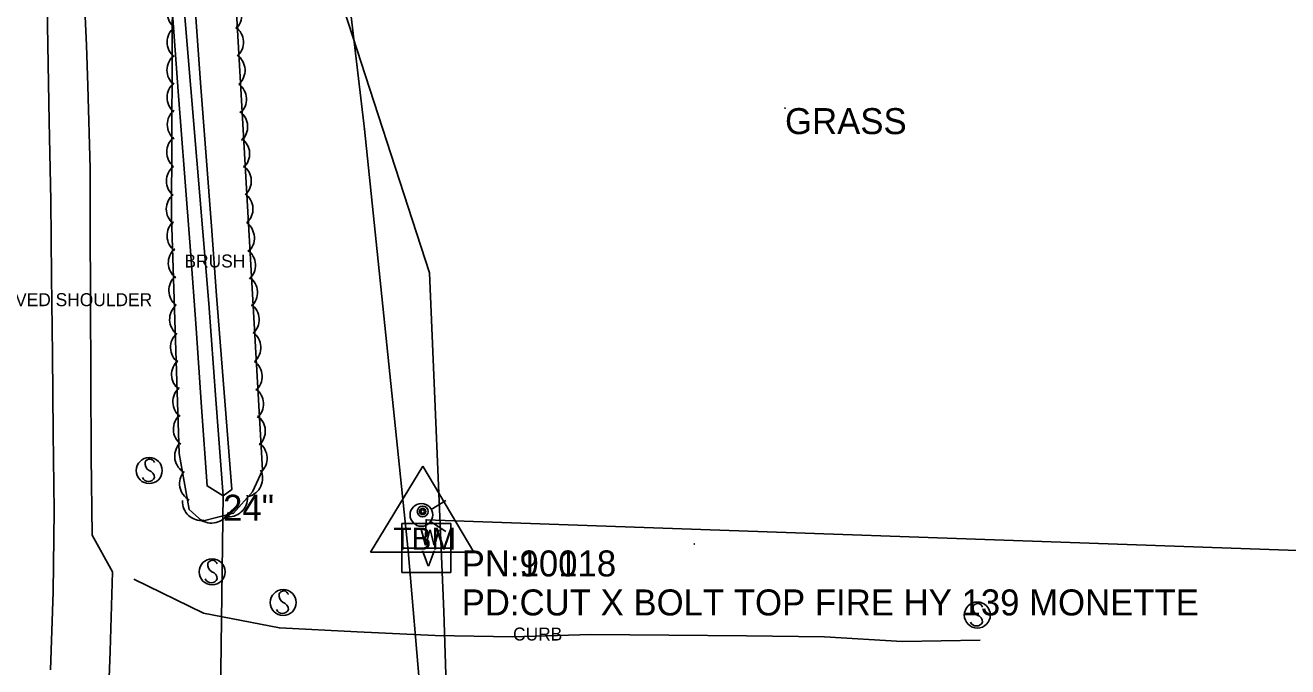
# Model space of a CAD drawing. Extents: x 1802180 to 1804859, y 572524 to 575172.
# Drawn here: x 1803540.3 to 1803783.3, y 574122.9 to 574246.4 of the extents above; entities that cross this region are included whole.
import ezdxf

# ---------------------------------------------------------------- set-up
doc = ezdxf.new("R2010")
doc.units = 0
for name, color, linetype in [('EX_EDGE_PAVEMENT', 7, 'Continuous'), ('EX_SHOULDER', 7, 'Continuous'), ('S_CURB_ANNOT', 7, 'Continuous'), ('S_DITCHLINE', 7, 'Continuous'), ('S_DRG_PT_SYM', 7, 'Continuous'), ('S_EDGE_PAVEMENT', 7, 'Continuous'), ('S_GAS_UTILITIES', 7, 'Continuous'), ('S_MSC_PT_SYM', 7, 'Continuous'), ('S_PRIMARY_CTL', 7, 'Continuous'), ('S_PRIMARY_CTL_ANNOT', 7, 'Continuous'), ('S_SHOULDER_ANNOT', 7, 'Continuous'), ('S_SIDE_DRAIN', 7, 'Continuous'), ('S_SIDE_DRAIN_ANNOT', 7, 'Continuous'), ('S_SIGN', 7, 'Continuous'), ('S_SURVEY_TEXT_ANNOT', 7, 'Continuous'), ('S_TREE', 7, 'Continuous'), ('S_TREE_ANNOT', 7, 'Continuous'), ('S_UTL_PT_SYM', 7, 'Continuous'), ('S_WATER_UTILITIES', 7, 'Continuous')]:
    doc.layers.add(name, color=color, linetype=linetype)

msp = doc.modelspace()

# ---------------------------------------------------------------- linework, layer by layer
at = {"layer": 'EX_EDGE_PAVEMENT'}
msp.add_lwpolyline([(1803545.13, 574122.38), (1803545.67, 574137.37), (1803545.82, 574152.93), (1803545.67, 574167.93), (1803545.52, 574183), (1803545.32, 574198), (1803545.22, 574212.65), (1803544.88, 574227.88), (1803544.63, 574242.61), (1803544.37, 574257.99)], dxfattribs=at)
at = {"layer": 'EX_SHOULDER'}
for points in [[(1803552.79, 574218.79), (1803552.32, 574234.7), (1803552.06, 574242.54), (1803551.37, 574257.72), (1803549.28, 574272.68), (1803547.76, 574287.55), (1803546.93, 574302.58), (1803546.47, 574317.58), (1803546.25, 574332.51), (1803545.94, 574347.57), (1803546.12, 574362.56), (1803545.82, 574377.55), (1803544.33, 574392.54), (1803543.97, 574407.55), (1803544.06, 574422.58), (1803543.55, 574437.52), (1803544.01, 574452.51), (1803543.95, 574467.53), (1803543.32, 574482.51)], [(1803539.39, 573989.74), (1803541.92, 574004.6), (1803544.28, 574019.59), (1803546.2, 574034.65), (1803547.92, 574049.68), (1803549.45, 574064.73), (1803550.58, 574079.78), (1803551.78, 574094.83), (1803555.06, 574095.6), (1803556.02, 574110.79), (1803556.63, 574125.93), (1803557.07, 574141.21), (1803553.14, 574148.24), (1803552.95, 574163.39), (1803552.87, 574178.39), (1803552.81, 574193.41), (1803552.74, 574208.36), (1803552.79, 574218.79)]]:
    msp.add_lwpolyline(points, dxfattribs=at)
at = {"layer": 'S_DITCHLINE'}
for points in [[(1803578.36, 574155.86), (1803575.27, 574157.74), (1803574.23, 574172.91), (1803573.19, 574188.07), (1803572.06, 574202.99), (1803570.92, 574217.9), (1803569.78, 574232.81), (1803568.65, 574247.72), (1803567.96, 574264.8), (1803564.64, 574280.02), (1803561.47, 574293.98), (1803558.97, 574310.39), (1803557.9, 574323.45), (1803556.83, 574336.52), (1803557.76, 574350.14)], [(1803578.36, 574155.86), (1803576.98, 574174.35), (1803575.6, 574192.85), (1803574.44, 574206.63), (1803573.29, 574220.41), (1803572.14, 574234.18), (1803570.99, 574247.96), (1803569.75, 574265.67), (1803567.48, 574280.25), (1803563.96, 574294.84), (1803561.78, 574311.07), (1803560.77, 574323.92), (1803559.75, 574336.77), (1803559.74, 574350.91), (1803557.76, 574350.14)], [(1803578.36, 574155.86), (1803580.03, 574157.04), (1803578.56, 574175.7), (1803577.1, 574194.36), (1803576.1, 574207.73), (1803575.1, 574221.1), (1803574.1, 574234.47), (1803573.1, 574247.84), (1803571.95, 574265.78), (1803569.07, 574280.63), (1803567.21, 574295.41), (1803565.01, 574310.96), (1803564.02, 574323.78), (1803563.04, 574336.6), (1803561.93, 574348.97), (1803559.74, 574350.91)]]:
    msp.add_lwpolyline(points, dxfattribs=at)
at = {"layer": 'S_DRG_PT_SYM'}
msp.add_lwpolyline([(1803578.35, 574156.04), (1803578.35, 574156.09), (1803578.35, 574156.04), (1803578.3, 574156.04), (1803578.35, 574156.04), (1803578.35, 574155.99), (1803578.35, 574156.04), (1803578.4, 574156.04)], dxfattribs=at)
at = {"layer": 'S_EDGE_PAVEMENT'}
msp.add_lwpolyline([(1803561.18, 574139.79), (1803574.61, 574133.23), (1803589.19, 574130.43), (1803604.16, 574129.67), (1803619.15, 574128.93), (1803634.14, 574128.71), (1803649.13, 574129.12), (1803664.13, 574129.01), (1803679.13, 574128.91), (1803694.13, 574128.72), (1803709.1, 574127.8), (1803724.1, 574128.08)], dxfattribs=at)
at = {"layer": 'S_GAS_UTILITIES'}
for p, q in [((1803618.09, 574198.71), (1803593.78, 574273.54)), ((1803620.84, 574133.58), (1803618.09, 574198.71)), ((1803622.65, 574080.31), (1803620.84, 574133.58))]:
    msp.add_line(p, q, dxfattribs=at)
at = {"layer": 'S_MSC_PT_SYM'}
msp.add_lwpolyline([(1803686.53, 574230.42), (1803686.53, 574230.47), (1803686.53, 574230.42), (1803686.48, 574230.42), (1803686.53, 574230.42), (1803686.53, 574230.37), (1803686.53, 574230.42), (1803686.58, 574230.42)], dxfattribs=at)
at = {"layer": 'S_PRIMARY_CTL'}
for p, q in [((1803616.78, 574161.53), (1803606.75, 574145.01)), ((1803616.78, 574161.53), (1803606.75, 574145.01)), ((1803616.78, 574161.53), (1803626.61, 574145.01)), ((1803616.78, 574161.53), (1803626.61, 574145.01)), ((1803606.75, 574145.01), (1803626.61, 574145.01)), ((1803606.75, 574145.01), (1803626.61, 574145.01))]:
    msp.add_line(p, q, dxfattribs=at)
for radius in [1.04, 1.04, 0.609, 0.609, 0.344, 0.344]:
    msp.add_circle((1803616.78, 574152.82), radius, dxfattribs=at)
at = {"layer": 'S_SIDE_DRAIN'}
msp.add_line((1803577.28, 574074.18), (1803578.35, 574156.04), dxfattribs=at)
at = {"layer": 'S_SIGN'}
for centre in [(1803564.14, 574160.69), (1803576.24, 574141.21), (1803589.93, 574135.3), (1803723.54, 574132.89)]:
    msp.add_circle(centre, 2.5, dxfattribs=at)
for centre, radius, start, end in [((1803564.83, 574162.02), 1.51, 167.1196, 241.9813), ((1803564.21, 574161.96), 0.952, 16.5258, 156.8957), ((1803563.99, 574159.87), 1.28, 204.641, 335.359), ((1803563.73, 574159.35), 1.4, 358.6529, 73.7063), ((1803576.92, 574142.54), 1.51, 167.1196, 241.9813), ((1803576.31, 574142.48), 0.952, 16.5258, 156.8957), ((1803576.08, 574140.39), 1.28, 204.641, 335.359), ((1803575.82, 574139.87), 1.4, 358.6529, 73.7063), ((1803590, 574136.57), 0.952, 16.5258, 156.8957), ((1803590.62, 574136.63), 1.51, 167.1196, 241.9813), ((1803589.52, 574133.96), 1.4, 358.6529, 73.7063), ((1803723.61, 574134.16), 0.952, 16.5258, 156.8957), ((1803589.77, 574134.48), 1.28, 204.641, 335.359), ((1803724.23, 574134.22), 1.51, 167.1196, 241.9813), ((1803723.13, 574131.55), 1.4, 358.6529, 73.7063), ((1803723.39, 574132.07), 1.28, 204.641, 335.359)]:
    msp.add_arc(centre, radius, start, end, dxfattribs=at)
at = {"layer": 'S_TREE'}
msp.add_lwpolyline([(1803578.71, 574288.41), (1803585.95, 574160.79), (1803584.01, 574156.59), (1803580.38, 574152.47), (1803574.33, 574150.93), (1803571.83, 574153.23), (1803569.9, 574164), (1803568.42, 574209.52), (1803568.63, 574255.13), (1803566.65, 574277.75), (1803565.55, 574283.98), (1803567.22, 574286.93), (1803569.89, 574288.1), (1803575.77, 574288.75), (1803578.71, 574288.41)], dxfattribs=at)
for centre, start, end in [((1803571.24, 574248.69), 128.9342, 230.5311), ((1803578.35, 574248.31), 312.4498, 54.0467), ((1803571.18, 574243.1), 128.9342, 230.5311), ((1803578.68, 574243.08), 312.4498, 54.0467), ((1803571.15, 574237.72), 128.9342, 230.5311), ((1803578.98, 574237.7), 312.4498, 54.0467), ((1803571.16, 574232.47), 128.9342, 230.5311), ((1803579.27, 574232.12), 312.4498, 54.0467), ((1803571.21, 574227.25), 128.9342, 230.5311), ((1803579.49, 574226.85), 312.4498, 54.0467), ((1803571.11, 574221.97), 128.9342, 230.5311), ((1803579.86, 574221.64), 312.4498, 54.0467), ((1803571.05, 574216.38), 128.9342, 230.5311), ((1803580.19, 574216.4), 312.4498, 54.0467), ((1803571.02, 574211), 128.9342, 230.5311), ((1803580.5, 574211.03), 312.4498, 54.0467), ((1803571.17, 574205.86), 131.0631, 232.66), ((1803580.78, 574205.45), 312.4498, 54.0467), ((1803571.41, 574200.64), 131.0631, 232.66), ((1803581.01, 574200.18), 312.4498, 54.0467), ((1803571.51, 574195.36), 131.0631, 232.66), ((1803581.38, 574194.96), 312.4498, 54.0467), ((1803571.66, 574189.77), 131.0631, 232.66), ((1803581.71, 574189.73), 312.4498, 54.0467), ((1803571.83, 574184.39), 131.0631, 232.66), ((1803582.01, 574184.35), 312.4498, 54.0467), ((1803572.04, 574179.15), 131.0631, 232.66), ((1803582.29, 574178.77), 312.4498, 54.0467), ((1803572.28, 574173.93), 131.0631, 232.66), ((1803582.52, 574173.5), 312.4498, 54.0467), ((1803572.38, 574168.65), 131.0631, 232.66), ((1803582.89, 574168.29), 312.4498, 54.0467), ((1803572.64, 574163.46), 139.3395, 240.9364), ((1803583.22, 574163.05), 312.4498, 54.0467), ((1803573.58, 574158.16), 139.3395, 240.9364), ((1803582.35, 574159.19), 284.4101, 26.007), ((1803574.13, 574154.69), 176.6148, 278.2117), ((1803579.44, 574155.39), 267.783, 9.3799), ((1803576.11, 574154.18), 233.5299, 335.1269)]:
    msp.add_arc(centre, 3.6, start, end, dxfattribs=at)
at = {"layer": 'S_UTL_PT_SYM'}
for points in [[(1803605.55, 574226.4), (1803605.55, 574226.45), (1803605.55, 574226.4), (1803605.5, 574226.4), (1803605.55, 574226.4), (1803605.55, 574226.35), (1803605.55, 574226.4), (1803605.6, 574226.4)], [(1803618.09, 574198.71), (1803618.09, 574198.76), (1803618.09, 574198.71), (1803618.04, 574198.71), (1803618.09, 574198.71), (1803618.09, 574198.66), (1803618.09, 574198.71), (1803618.14, 574198.71)], [(1803617.45, 574151.21), (1803617.45, 574151.26), (1803617.45, 574151.21), (1803617.4, 574151.21), (1803617.45, 574151.21), (1803617.45, 574151.16), (1803617.45, 574151.21), (1803617.5, 574151.21)], [(1803613.98, 574145.26), (1803613.98, 574145.31), (1803613.98, 574145.26), (1803613.93, 574145.26), (1803613.98, 574145.26), (1803613.98, 574145.21), (1803613.98, 574145.26), (1803614.03, 574145.26)], [(1803613.99, 574145.37), (1803613.99, 574145.42), (1803613.99, 574145.37), (1803613.94, 574145.37), (1803613.99, 574145.37), (1803613.99, 574145.32), (1803613.99, 574145.37), (1803614.04, 574145.37)], [(1803617.28, 574146.43), (1803617.28, 574146.48), (1803617.28, 574146.43), (1803617.23, 574146.43), (1803617.28, 574146.43), (1803617.28, 574146.38), (1803617.28, 574146.43), (1803617.33, 574146.43)], [(1803669.06, 574146.57), (1803669.06, 574146.62), (1803669.06, 574146.57), (1803669.01, 574146.57), (1803669.06, 574146.57), (1803669.06, 574146.52), (1803669.06, 574146.57), (1803669.11, 574146.57)], [(1803669.06, 574146.57), (1803669.06, 574146.62), (1803669.06, 574146.57), (1803669.01, 574146.57), (1803669.06, 574146.57), (1803669.06, 574146.52), (1803669.06, 574146.57), (1803669.11, 574146.57)], [(1803620.84, 574133.58), (1803620.84, 574133.63), (1803620.84, 574133.58), (1803620.79, 574133.58), (1803620.84, 574133.58), (1803620.84, 574133.53), (1803620.84, 574133.58), (1803620.89, 574133.58)]]:
    msp.add_lwpolyline(points, dxfattribs=at)
at = {"layer": 'S_WATER_UTILITIES'}
for p, q in [((1803605.55, 574226.4), (1803589.68, 574362.39)), ((1803613.98, 574145.26), (1803605.55, 574226.4)), ((1803618.44, 574153.22), (1803621.26, 574154.95)), ((1803612.75, 574150.48), (1803622.17, 574150.48)), ((1803612.75, 574141.06), (1803612.75, 574150.48)), ((1803617.28, 574146.43), (1803617.45, 574151.21)), ((1803617.45, 574151.21), (1803789.07, 574145.16)), ((1803618.31, 574150.91), (1803621.22, 574148.98)), ((1803622.17, 574150.48), (1803622.17, 574141.06)), ((1803612.75, 574145.79), (1803622.17, 574145.79)), ((1803617.7, 574102.18), (1803613.98, 574145.26)), ((1803622.17, 574141.06), (1803612.75, 574141.06))]:
    msp.add_line(p, q, dxfattribs=at)
msp.add_circle((1803616.53, 574152.16), 2.18, dxfattribs=at)

# ---------------------------------------------------------------- texts
at = {"layer": 'S_CURB_ANNOT'}
msp.add_text('CURB', height=2.5, dxfattribs=at).set_placement((1803634.17, 574127.99))
at = {"layer": 'S_PRIMARY_CTL'}
msp.add_text('TBM', height=4.287, rotation=360, dxfattribs=at).set_placement((1803611.13, 574145.44))
msp.add_text('TBM', height=4.287, rotation=360, dxfattribs=at).set_placement((1803611.13, 574145.44))
at = {"layer": 'S_PRIMARY_CTL_ANNOT'}
for s, p in [('PN:901', (1803624.28, 574140.32)), ('PN:10018', (1803624.28, 574140.32)), ('PD:CUT X BOLT TOP FIRE HY 139 MONETTE', (1803624.28, 574132.82)), ('PD:', (1803624.28, 574132.82))]:
    msp.add_text(s, height=5, dxfattribs=at).set_placement(p)
at = {"layer": 'S_SHOULDER_ANNOT'}
msp.add_text('PAVED SHOULDER', height=2.5, dxfattribs=at).set_placement((1803533.86, 574192.32))
at = {"layer": 'S_SIDE_DRAIN_ANNOT'}
msp.add_text('24"       ', height=5, dxfattribs=at).set_placement((1803578.35, 574151.04))
at = {"layer": 'S_SURVEY_TEXT_ANNOT'}
msp.add_text('GRASS ', height=5, dxfattribs=at).set_placement((1803686.53, 574225.42))
at = {"layer": 'S_TREE_ANNOT'}
msp.add_text('BRUSH', height=2.5, dxfattribs=at).set_placement((1803570.92, 574199.76))
at = {"layer": 'S_WATER_UTILITIES'}
for s, p in [('W', (1803616.3, 574146.32)), ('V', (1803616.54, 574142.26))]:
    msp.add_text(s, height=3, rotation=360, dxfattribs=at).set_placement(p)

doc.saveas('drawing.dxf')
